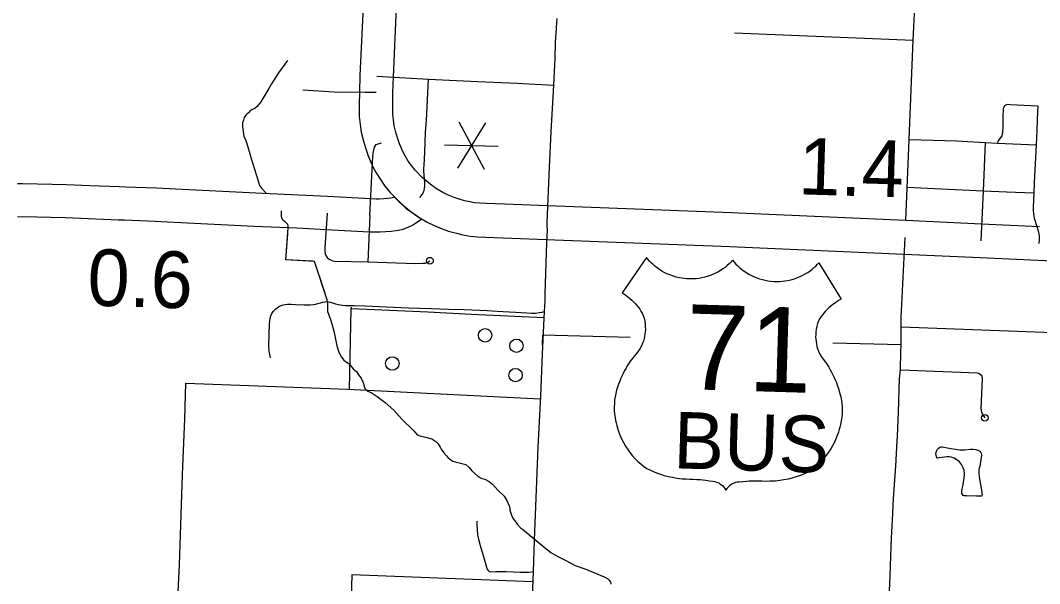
# Model space of a CAD drawing. Extents: x 653372 to 905732, y 627442 to 787275.
# Drawn here: x 658495 to 666097, y 733242 to 737443 of the extents above; entities that cross this region are included whole.
import ezdxf

# ---------------------------------------------------------------- set-up
doc = ezdxf.new("R2010")
doc.units = 0
for name, color, linetype in [('10', 7, 'Continuous'), ('15', 7, 'Continuous'), ('22', 7, 'Continuous'), ('33', 7, 'Continuous'), ('34', 7, 'Continuous'), ('35', 7, 'Continuous'), ('43', 7, 'Continuous'), ('48', 7, 'Continuous'), ('56', 7, 'Continuous'), ('6', 7, 'Continuous')]:
    doc.layers.add(name, color=color, linetype=linetype)

msp = doc.modelspace()

# ---------------------------------------------------------------- linework, layer by layer
at = {"layer": '10'}
for points in [[(658473.1, 736226), (658512.2, 736226.5), (658731.5, 736222.3), (658837.4, 736219.1), (659013, 736212.1), (659232.7, 736203), (659278.4, 736202.3), (659510.8, 736192.8), (659603.8, 736187.9), (660249.8, 736155.8), (660568.7, 736141.5), (660788.3, 736130.6), (661106.5, 736113.6), (661145.9, 736112.6), (661170.8, 736112.8), (661205.4, 736114.9), (661236.2, 736117), (661258.3, 736119.9), (661270.3, 736122.1), (661284.1, 736127.5), (661370.9, 736042.4), (661489.2, 735961.2)], [(661489.2, 735961.2), (661464.4, 735942.3), (661420.8, 735915.1), (661384.2, 735898.2), (661339, 735880.6), (661297.2, 735872.8), (661260.9, 735868.1), (661221.7, 735865.4), (661179.4, 735862.8), (661143.8, 735862.5), (661096.6, 735863.7), (660775.4, 735881), (660557, 735891.8), (660238, 735906), (659590.9, 735938.3), (659499.1, 735943.1), (659271.3, 735952.4), (659225.7, 735953.1), (659002.9, 735962.3), (658828.6, 735969.3), (658725.3, 735972.4), (658511.6, 735976.5), (658472.8, 735975.9)]]:
    msp.add_lwpolyline(points, dxfattribs=at)
at = {"layer": '15'}
for points in [[(661050.5, 737546.6), (661027.4, 737030.7), (661023.6, 736909.4), (661022.1, 736808.1), (661021.4, 736726.6), (661028.8, 736666.6), (661037.6, 736608.5), (661051.3, 736551.9), (661069.5, 736491.2), (661088.7, 736432.9), (661124.5, 736350.7), (661147.9, 736306.1), (661179.8, 736255.9), (661213.4, 736207.2), (661253.7, 736159.8), (661320.4, 736088.9), (661397.6, 736023.9), (661462.6, 735976.8), (661528.1, 735938.5), (661576.8, 735914.8), (661640.1, 735887.7), (661686.7, 735871.6), (661746.4, 735855.3), (661795.3, 735844.1), (661848.6, 735834.3), (661905.4, 735829.5), (661964.3, 735826.8), (662161.5, 735819.2), (662417.4, 735809.2), (663787.3, 735756.5), (663840.7, 735754.1), (665087.3, 735699.3), (665652.6, 735674.4), (666085.4, 735653.7), (667086.2, 735607.7)], [(666097.1, 735903.4), (665664.1, 735924.1), (665098.3, 735949.1), (663851.9, 736003.9), (663797.8, 736006.3), (662427.1, 736059), (662171.2, 736069), (661974.8, 736076.6), (661921.5, 736079), (661881.8, 736082.4), (661845.8, 736089), (661807.2, 736097.8), (661760.5, 736110.6), (661730.2, 736121), (661680.8, 736142.2), (661646.1, 736159.1), (661599.5, 736186.4), (661551.7, 736221), (661492.5, 736270.8), (661440.1, 736326.5), (661412.1, 736359.5), (661388.3, 736394), (661364.4, 736431.6), (661350.1, 736458.9), (661322.6, 736522.1), (661308, 736566.3), (661292.7, 736617.3), (661283.1, 736656.7), (661276.5, 736700.5), (661271.6, 736740.8), (661272.1, 736805.2), (661273.6, 736903.6), (661277.3, 737021.2), (661300.4, 737539.2)]]:
    msp.add_lwpolyline(points, dxfattribs=at)
at = {"layer": '22'}
for points in [[(663807.3, 735653.3), (663793.7, 735638.9), (663780.8, 735626.4), (663766.1, 735613.4), (663750.3, 735600.7), (663735, 735589.6), (663716.6, 735577.5), (663696.9, 735566), (663674.4, 735554.5), (663646.1, 735542.4), (663624.3, 735534.7), (663599.8, 735527.5), (663577.4, 735522.4), (663556.8, 735518.8), (663535.1, 735516.1), (663515.2, 735514.7), (663488, 735514.2), (663465.9, 735515.2), (663446.7, 735516.9), (663428.4, 735519.4), (663409.9, 735522.8), (663386.7, 735528.2), (663365.3, 735534.5), (663339.3, 735543.8), (663317.3, 735553.3), (663297.3, 735563.2), (663279.1, 735573.5), (663262.2, 735584), (663243.5, 735597.2), (663226.3, 735610.6), (663211.6, 735623.3), (663199.2, 735635.1), (663186.5, 735648), (663174.2, 735661.9), (663164.2, 735674), (662983.2, 735411.7), (662995.3, 735403.9), (663009.7, 735393.9), (663023.4, 735383.5), (663041.5, 735368.5), (663056, 735355.3), (663068.8, 735342.6), (663081.7, 735328.6), (663095, 735312.9), (663104.5, 735300.7), (663113.9, 735287.9), (663123.3, 735273.9), (663132.4, 735259.1), (663140.8, 735241.8), (663146.9, 735220.8), (663151.3, 735199.9), (663154.5, 735177.7), (663156, 735157.2), (663156.1, 735137.3), (663155, 735118.8), (663153.3, 735104), (663150.3, 735085.9), (663146.4, 735068.8), (663141.1, 735050.4), (663135.4, 735034.3), (663127.7, 735016.2), (663115.7, 734993), (663103.7, 734974.8), (663089.2, 734958.5), (663071.7, 734937.3), (663057.3, 734918.6), (663043.9, 734900), (663031.6, 734881.6), (663021.2, 734865.1), (663012, 734849.7), (663001.7, 734831.3), (662990.6, 734809.8), (662980.6, 734788.7), (662973.6, 734773), (662965.4, 734752.9), (662956.2, 734728.2), (662948.9, 734707.7), (662941.9, 734685.3), (662935.3, 734659.2), (662930.8, 734636), (662927.2, 734611.7), (662924.9, 734585.1), (662924, 734560.1), (662924.4, 734535.6), (662926.5, 734506.8), (662930.1, 734479.5), (662934, 734458.7), (662938.2, 734440.6), (662943.5, 734420), (662950.6, 734394.3), (662961.2, 734363.2), (662970.3, 734340.2), (662981, 734316.5), (662992.9, 734293.3), (663008.4, 734266.5), (663024.5, 734241.8), (663040.2, 734220.3), (663058, 734198.2), (663081.2, 734172.7), (663100.9, 734153.3), (663121.3, 734135.2)], [(663807.3, 735653.3), (663820, 735638.1), (663832.2, 735624.8), (663846.1, 735611), (663861.1, 735597.4), (663875.7, 735585.4), (663893.3, 735572.2), (663912.3, 735559.5), (663934, 735546.7), (663961.7, 735532.9), (663982.9, 735523.9), (664006.9, 735515.3), (664029, 735508.9), (664049.3, 735504), (664070.8, 735500.1), (664090.6, 735497.4), (664117.8, 735495.3), (664139.9, 735494.9), (664159.2, 735495.5), (664177.5, 735496.9), (664196.2, 735499.1), (664219.7, 735503.2), (664241.4, 735508.2), (664268, 735516), (664290.5, 735524.1), (664311, 735532.8), (664329.9, 735541.9), (664347.3, 735551.4), (664366.8, 735563.4), (664384.7, 735575.8), (664400.2, 735587.7), (664413.3, 735598.6), (664426.7, 735610.8), (664439.8, 735623.9), (664450.5, 735635.4), (664615.5, 735362.6), (664602.9, 735355.6), (664587.9, 735346.5), (664573.7, 735337), (664554.7, 735323.1), (664539.4, 735310.7), (664525.9, 735298.8), (664512.1, 735285.6), (664497.9, 735270.8), (664487.7, 735259.2), (664477.6, 735246.9), (664467.4, 735233.5), (664457.4, 735219.3), (664448, 735202.6), (664440.6, 735181.9), (664434.9, 735161.4), (664430.4, 735139.4), (664427.8, 735119), (664426.5, 735099.2), (664426.4, 735080.7), (664427.2, 735065.7), (664429.1, 735047.5), (664431.9, 735030.2), (664436.2, 735011.5), (664440.9, 734995.1), (664447.5, 734976.6), (664458, 734952.7), (664469, 734933.8), (664482.4, 734916.7), (664498.7, 734894.4), (664511.9, 734875), (664524.1, 734855.5), (664535.3, 734836.5), (664544.7, 734819.4), (664553, 734803.4), (664562.1, 734784.4), (664571.9, 734762.3), (664580.7, 734740.7), (664586.7, 734724.6), (664593.7, 734704), (664601.4, 734678.8), (664607.5, 734657.9), (664613.1, 734635.1), (664618.1, 734608.6), (664621.3, 734585.2), (664623.3, 734560.7), (664624.1, 734534.1), (664623.5, 734509.1), (664621.6, 734484.7), (664617.8, 734456), (664612.5, 734429), (664607.4, 734408.5), (664602.2, 734390.6), (664595.6, 734370.4), (664586.9, 734345.2), (664574.5, 734314.7), (664564, 734292.3), (664551.9, 734269.4), (664538.7, 734246.8), (664521.6, 734221), (664504.1, 734197.4), (664487.1, 734176.9), (664468, 734155.9), (664443.3, 734131.8), (664422.4, 734113.6), (664401, 734096.7)], [(663121.3, 734135.2), (663142.5, 734118.1), (663168.1, 734100.3), (663200.4, 734084.7), (663238.2, 734068.8), (663269.2, 734057.7), (663297.1, 734049.1), (663328.7, 734040.8), (663358.4, 734034.4), (663390.4, 734029), (663430.7, 734024.3), (663461.6, 734022.3), (663488.1, 734021.6), (663513.8, 734020.6), (663539.6, 734019), (663564, 734017.1), (663585.3, 734015), (663606.2, 734012.6), (663633, 734009), (663659.2, 734004.9), (663674.9, 734002.2), (663687.8, 733999.3), (663703.4, 733992.3), (663712.2, 733987), (663720, 733981.6), (663730.5, 733972.6), (663740.5, 733961.8), (663748.6, 733950.8), (663755.8, 733938.1)], [(664401, 734096.7), (664378.8, 734081), (664352.2, 734064.7), (664319.1, 734051.1), (664280.3, 734037.5), (664248.8, 734028.3), (664220.4, 734021.3), (664188.4, 734015), (664158.3, 734010.4), (664126.1, 734006.9), (664085.5, 734004.6), (664054.6, 734004.5), (664028.1, 734005.4), (664002.3, 734005.9), (663976.5, 734005.9), (663952.1, 734005.4), (663930.7, 734004.6), (663909.6, 734003.5), (663882.7, 734001.5), (663856.3, 733999), (663840.5, 733997.3), (663827.4, 733995.1), (663811.4, 733989.1), (663802.3, 733984.3), (663794.2, 733979.4), (663783.2, 733971), (663772.6, 733960.8), (663763.8, 733950.3), (663755.8, 733938.1)]]:
    msp.add_lwpolyline(points, dxfattribs=at)
at = {"layer": '33'}
for points in [[(665098.9, 735949), (665124.4, 736553.4), (665154.1, 737295.5), (665167.7, 737594.6)], [(662494.7, 737458), (662493.3, 737428.2), (662491, 737386), (662484.7, 737277.4), (662480.2, 737161.4), (662470, 736960.2), (662450.9, 736612.5), (662438.3, 736348.1), (662422.3, 735934.1)], [(663820.1, 737351), (665154.1, 737295.5)], [(661152.3, 737026), (661539.1, 737005.6), (661905.2, 736988), (662200.5, 736974), (662470, 736960.2)], [(661474.7, 736122.5), (661492, 736145.4), (661503.9, 736167.6), (661510.1, 736185.9), (661511.8, 736208), (661511.7, 736238.3), (661507.5, 736285.6), (661504.5, 736323.7), (661505, 736339.3), (661505.7, 736364), (661511.8, 736459.8), (661517.2, 736608.6), (661523.9, 736695.9), (661539.1, 737005.6)], [(660600.8, 736925.6), (660833.9, 736910.9), (661066.6, 736906.5), (661148.6, 736906.5)], [(666082.9, 736803.9), (665877.2, 736813.7), (665855.2, 736814.4), (665845.9, 736811.7), (665835.9, 736806.1), (665831.3, 736799.4), (665828.7, 736793.1), (665825.5, 736783.4), (665824.1, 736771.2), (665823.2, 736736.3), (665822, 736649.2), (665819.8, 736609.1), (665814.6, 736582.4), (665803.3, 736563.6), (665793.6, 736551.7), (665788, 736543.5), (665784.8, 736535.8), (665783.6, 736527)], [(666082.9, 736804.1), (666082.9, 736803.9), (666081.7, 736765.9), (666076.4, 736623.2), (666072.3, 736514.9), (666057.4, 736231.4), (666053.6, 736153.2), (666049, 736049.9), (666047.7, 736024), (666050, 736003.3), (666057.3, 735968.8), (666078.2, 735898.2), (666088.4, 735862.2), (666090.4, 735847.4), (666092.5, 735836.3), (666093.1, 735810.8), (666091.2, 735778.6)], [(661101.5, 735988.6), (661123.7, 736426.9), (661128.7, 736464.9), (661136.6, 736496.7), (661143, 736508.7), (661149.6, 736516), (661162.3, 736521), (661188.7, 736528.7)], [(665124.4, 736553.4), (665476.2, 736543.6), (665690.2, 736531.3), (665783.6, 736527), (666072.3, 736514.9)], [(665690.2, 736531.3), (665677, 736169.2), (665658.4, 735799.3)], [(666053.6, 736153.2), (665850.3, 736162.6), (665677, 736169.2), (665109.3, 736195.3)], [(660781.8, 736005.8), (660766.2, 735747.5), (660765.3, 735717.9), (660768.1, 735702.7), (660773, 735688.8), (660783.1, 735674.6), (660797.8, 735662.4), (660812.7, 735653.4), (660825.7, 735649.7), (660840.7, 735646.6), (661086.5, 735641.9), (661443.8, 735630.5), (661497.7, 735630.8), (661514.9, 735632.9), (661536.8, 735640.8), (661549.6, 735650.3)], [(661101.5, 735988.6), (661086.5, 735641.9)], [(662422.3, 735934.1), (662422, 735910.3), (662423.9, 735879.1), (662419.7, 735786.8), (662405.4, 735404), (662405.2, 735350), (662401.3, 735272.3), (662387, 734955.8), (662374, 734640.8), (662353.4, 734259.6), (662326.9, 733566.5), (662319.2, 733332.9), (662292, 732638.7)], [(664948.1, 732373.3), (664961.4, 732841.6), (664969, 733050.4), (664974.7, 733157.7), (664975.3, 733173.2), (664976.2, 733188.7), (664981.7, 733300), (664987.2, 733447.3), (664989.1, 733516.1), (664993.2, 733582.7), (664999.8, 733714.4), (665006.6, 733875.6), (665025.1, 734116.6), (665035.4, 734305.6), (665037.6, 734339.8), (665045.2, 734520.9), (665052.7, 734770), (665059.8, 734837.5), (665062, 734970.5), (665063, 735025.3), (665065.2, 735226.5), (665092.8, 735824.2)], [(665059.8, 734837.5), (665633.3, 734814.3), (665644, 734811.5), (665658.1, 734799.1), (665665, 734788.1), (665668.1, 734772.4), (665658.9, 734546.7), (665664.1, 734520.1), (665667.4, 734508), (665687.9, 734478.5)]]:
    msp.add_lwpolyline(points, dxfattribs=at)
for centre in [(661549.6, 735650.3), (665687.9, 734478.5)]:
    msp.add_circle(centre, 25, dxfattribs=at)
at = {"layer": '34'}
for points in [[(660360.2, 734924.6), (660354.1, 734950.2), (660350.8, 734975.8), (660348.5, 735014.8), (660349.2, 735096.6), (660354, 735178.3), (660358.7, 735221.1), (660363.9, 735238.9), (660373.9, 735261.3), (660382.4, 735273.8), (660399.1, 735290.7), (660411.6, 735301.3), (660426.4, 735310.7), (660441.1, 735316.1), (660454.6, 735320.9), (660469.2, 735323.4), (660487.8, 735325.7), (660513.9, 735325.5), (660546.9, 735324.5), (660611.3, 735322), (660655.6, 735321.2), (660680.1, 735323.4), (660697, 735325.8), (660722.7, 735333.1), (660750.8, 735341), (660766, 735344), (660778.2, 735345.4), (660784, 735345.2), (660804.8, 735342.2), (660823.2, 735337.1), (660844.5, 735329.5), (660867.5, 735323.5), (660883.1, 735320.2), (660897.5, 735318), (660920.1, 735316.7), (660943.9, 735316), (660987.2, 735315.9), (661063.1, 735313), (661121, 735310.1), (661228.3, 735306.3), (661390.2, 735299.1), (661472.5, 735296.7), (661561.1, 735292.8), (661624.4, 735291.5), (661687.2, 735289.1), (661803.8, 735285.6), (661861.7, 735283.8), (661922.6, 735280.8), (661975.3, 735278.1), (662049.8, 735274.7), (662188.7, 735265.3), (662271, 735260.5), (662306.9, 735258.3), (662337.1, 735259.7), (662364.5, 735263.5), (662385.5, 735267.5), (662401.3, 735272.3)], [(661898.7, 733707.4), (661899.1, 733676.7), (661901.3, 733645.3), (661905.2, 733602.4), (661911.3, 733572.1), (661923.3, 733526.4), (661950.6, 733433.5), (661971.9, 733365.4), (661977.5, 733349.4), (661983.4, 733340), (661988.5, 733335.2), (661998.2, 733330.5)], [(661998.2, 733330.5), (662040.4, 733331.2), (662064.8, 733332.3), (662118.2, 733331.4), (662222.9, 733327.6), (662286.1, 733327.6), (662306, 733328.9), (662319.2, 733332.9)]]:
    msp.add_lwpolyline(points, dxfattribs=at)
at = {"layer": '35'}
for points in [[(660487.3, 737144.3), (660421.1, 737051.1), (660368.1, 736970.4), (660348.2, 736934.3), (660319, 736885.6), (660288.8, 736835.9), (660260, 736801.1), (660243.7, 736785.7), (660235.6, 736783), (660220.5, 736775.5), (660206.4, 736766), (660195.1, 736753.5), (660184.9, 736743.9), (660176.7, 736736.2), (660164.4, 736719.7), (660157.8, 736699.6), (660151.2, 736678), (660150.4, 736651.2), (660156.2, 736613.4), (660162.2, 736580.5), (660177, 736547.3), (660192.4, 736499.2), (660216.6, 736412.2), (660266.4, 736254.6), (660278.9, 736210.6), (660292.2, 736192.3), (660330.1, 736152.2)], [(660784.7, 735345.4), (660785.8, 735272.3), (660805.3, 735219.6), (660821.6, 735163.1), (660834.2, 735115.6), (660855.2, 735014.9), (660868.8, 734968.4), (660889.7, 734931.7), (660907, 734907.2), (660946.3, 734882), (660977.2, 734844), (661001.6, 734824.3), (661016.8, 734798.8), (661037.1, 734773.1), (661048.3, 734747.8), (661055.7, 734727.5), (661059.2, 734709.4), (661068.7, 734691.1), (661084.3, 734677.6), (661110, 734667.8), (661155.2, 734638.4), (661214.5, 734592.1), (661280.9, 734535), (661338.9, 734469.2), (661428.4, 734381.4), (661454.5, 734352.6), (661482.2, 734340.8), (661516, 734332.8), (661563.7, 734321.3), (661593.2, 734302.4), (661609.6, 734284.9), (661624.9, 734258.4), (661633.4, 734244.1), (661653.7, 734217.5), (661673, 734195.9), (661685.6, 734179.5), (661705.1, 734164.9), (661719.8, 734154.4), (661736.7, 734148.9), (661788.4, 734138.3), (661818.2, 734129.4), (661841.5, 734106.7), (661861.3, 734082.6), (661903.3, 734046.5), (661927.8, 734029.7), (661939.7, 734025.3), (661958.5, 734019.8), (661990, 734002.8), (662015.4, 733983), (662056.1, 733937.7), (662102.9, 733894.3), (662122.9, 733862.6), (662140.7, 733822.1), (662145.2, 733804.9), (662144.8, 733791.9), (662149.3, 733774.7), (662156.7, 733752.5), (662168, 733730.1), (662201.6, 733683.1), (662225.9, 733657.3), (662238.6, 733647.9), (662327.3, 733576.6)], [(665527.6, 734105.1), (665514, 734130.8), (665498.3, 734149.9), (665478.4, 734165.5), (665459.5, 734177.5), (665436.9, 734184.2), (665423.2, 734187), (665406.3, 734186.8), (665388.2, 734184.3), (665348.5, 734179.6), (665337, 734178.1), (665331.1, 734180.7), (665327.1, 734186.9), (665324.4, 734199), (665323.6, 734213.4), (665327.2, 734230.7), (665334.8, 734243.7), (665343.5, 734253.1), (665353.8, 734258.2), (665362.9, 734260.9), (665368.9, 734260.7), (665422.1, 734251.9), (665483.7, 734242.8), (665501.6, 734239.9), (665516.6, 734238.9), (665525, 734238.6), (665540.1, 734239.9), (665581.1, 734244.1), (665602.1, 734244.1), (665621.8, 734241.1), (665636.7, 734237), (665649.7, 734230), (665657.8, 734220.8), (665660.6, 734213.5), (665663.4, 734205), (665663.8, 734200.2), (665652.8, 734132)], [(665652.8, 734132), (665649.8, 734114.1), (665647.1, 734103.3), (665643.7, 734091.4), (665642.8, 734080.6), (665643.4, 734060.2), (665648.2, 734020.4), (665660, 733952.7), (665668, 733900.2), (665666.7, 733896.6), (665664.3, 733894.3), (665661.8, 733893.2), (665625.8, 733893.7), (665552, 733895.9), (665533.4, 733897), (665527.5, 733899.6), (665522.3, 733906.4), (665517.1, 733913.2), (665516.1, 733922.2), (665517.1, 733935.4), (665526.3, 733980.2), (665533.8, 734031), (665535.8, 734058.6), (665533.1, 734086.9), (665527.6, 734105.1)], [(662327.3, 733576.6), (662400, 733516.6), (662451.4, 733474.3), (662502.3, 733443), (662563.5, 733414.8), (662632.9, 733376.2), (662705.3, 733352.7), (662772.4, 733323.5), (662849.6, 733293.2), (662876.4, 733277.9), (662885.4, 733266.6), (662896, 733252.6), (662899.2, 733245.8), (662899.8, 733237.2)]]:
    msp.add_lwpolyline(points, dxfattribs=at)
at = {"layer": '43'}
for points in [[(660784.7, 735345.4), (660784.7, 735345.5), (660784.1, 735356.5), (660783.7, 735358.4), (660689, 735645.6), (660474.4, 735656.7), (660492.6, 735895.7), (660493, 735910.9), (660489.1, 735919.3), (660479.3, 735929.7), (660466.4, 735942.9), (660452.9, 735953), (660446.4, 735963.7), (660442.8, 735980.8), (660442.7, 736022)], [(660674.6, 735646.4), (660474.4, 735656.7), (660489.2, 735851.7)], [(660784.7, 735345.4), (660784.7, 735345.5), (660784.1, 735356.5), (660783.7, 735358.4), (660725.8, 735534)]]:
    msp.add_lwpolyline(points, dxfattribs=at)
at = {"layer": '48'}
for p, q in [((661964.2, 736679.7), (661753.9, 736339.5)), ((661764.3, 736685.7), (661953.8, 736333.5)), ((661659.2, 736515.6), (662059, 736503.6))]:
    msp.add_line(p, q, dxfattribs=at)
at = {"layer": '56'}
for centre in [(661961.2, 735093.8), (662194.7, 735015.5), (661269, 734883.5), (662188.1, 734796.9)]:
    msp.add_circle(centre, 50, dxfattribs=at)
at = {"layer": '6'}
for points in [[(660950.5, 734691.9), (660961.2, 735293.7), (661533, 735268.5), (661858.3, 735251.8), (662399.2, 735225.8)], [(660962.9, 735304.2), (660962.2, 735292.6)], [(665063, 735024.6), (665064.4, 735156), (666396.4, 735107), (666365.2, 734453.3), (667284.9, 734424.1), (667293.1, 734830.3), (667708.6, 734819.7), (667721.6, 735022.7), (667931.2, 735008.7), (667928.9, 734935.9), (668123, 734922.6), (668258.7, 734917.3), (668489.3, 735211.3), (668855.1, 735189.7), (668812.2, 735018.1), (668927.5, 735014)], [(662389.5, 735023.7), (662392.1, 735097.9), (663043.2, 735080)], [(664555.6, 735038.5), (665063, 735024.6)], [(660967.1, 733307.7), (660928.4, 732019.4), (660291.3, 732042), (659948.9, 732059.3), (659616.3, 732073.5), (659682.4, 733381.4), (659703.8, 734056.5), (659720.1, 734471.5), (659729.1, 734736.3), (660934.1, 734692.5), (662372.8, 734619.5)], [(662316.1, 733254.8), (660967.1, 733307.7)]]:
    msp.add_lwpolyline(points, dxfattribs=at)

# ---------------------------------------------------------------- texts
at = {"layer": '22'}
for s, height, p in [('71', 633.6, (663447.7, 734692.4)), ('BUS', 422.4, (663361.4, 734102.2))]:
    msp.add_text(s, height=height, rotation=358.28003, dxfattribs=at).set_placement(p)
at = {"layer": '48'}
for s, p in [('1.4', (664293.4, 736145.9)), ('0.6', (658990.2, 735316.6))]:
    msp.add_text(s, height=422.4, rotation=358.28003, dxfattribs=at).set_placement(p)

doc.saveas('drawing.dxf')
